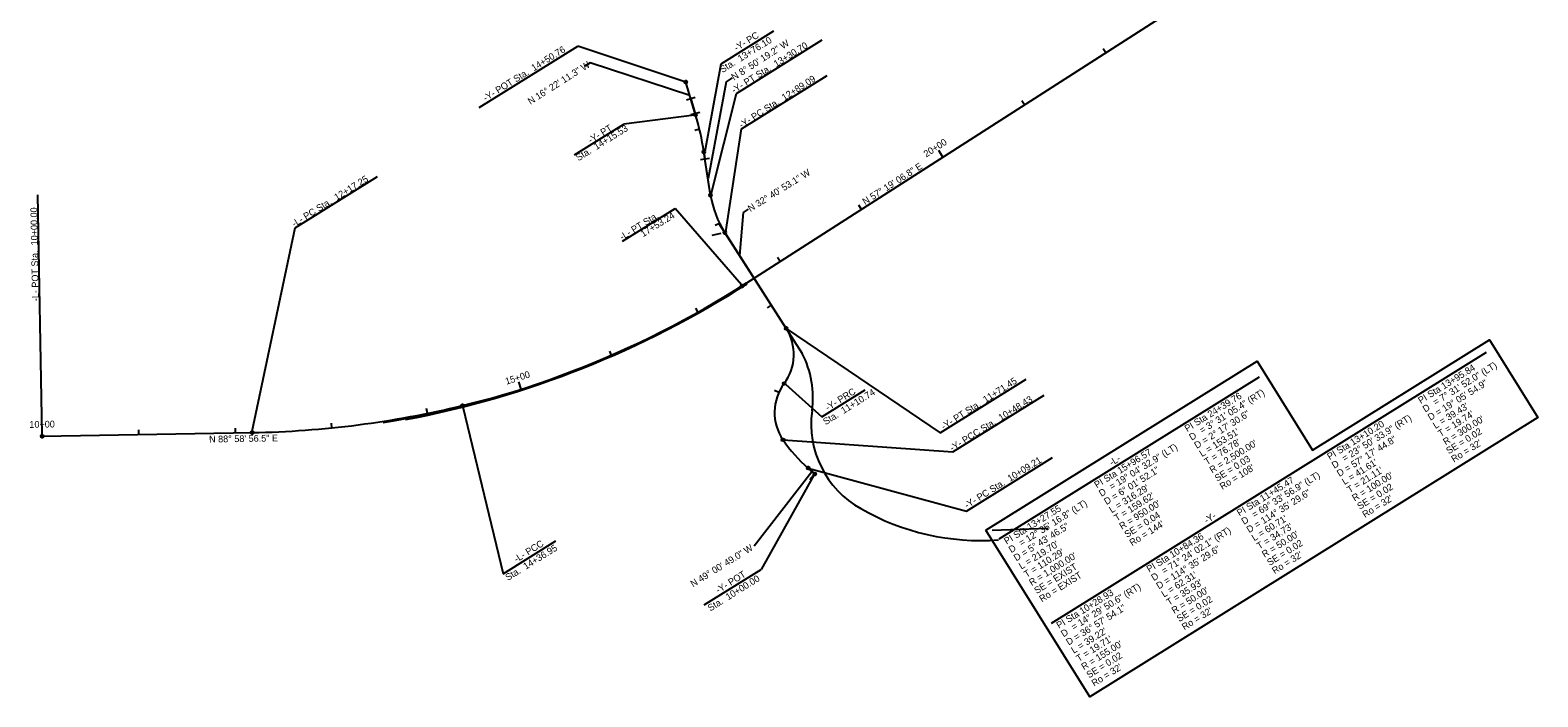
# Model space of a CAD drawing. Extents: x 2045940 to 2048976, y 757914 to 760106.
# Drawn here: x 2045940 to 2047500, y 757925 to 758615 of the extents above; entities that cross this region are included whole.
import ezdxf

# ---------------------------------------------------------------- set-up
doc = ezdxf.new("R2010")
doc.units = 0
for name, color, linetype in [('Prop AutoTurn Projected Path', 7, 'Continuous'), ('Prop Conc 1ft 6in Curb and Gutter', 7, 'Continuous'), ('Prop Conc 5in Monolithic Surface Mount Island', 7, 'Continuous'), ('Prop Dimension', 7, 'Continuous'), ('Prop Horizontal Alignment', 7, 'Continuous'), ('Prop Lane Lines', 7, 'Continuous'), ('Prop Paint Stripe', 7, 'Continuous'), ('Prop Superelevation  Arrow CELL', 7, 'Continuous'), ('Prop Superelevation Label', 7, 'Continuous'), ('Prop Terminator CELL', 7, 'Continuous'), ('Typical Terminator CELL', 7, 'Continuous')]:
    doc.layers.add(name, color=color, linetype=linetype)

msp = doc.modelspace()

# ---------------------------------------------------------------- linework, layer by layer
at = {"layer": 'Prop AutoTurn Projected Path'}
for p, q in [((2046997.2, 758001.6), (2047447, 758281.9)), ((2046943, 758088.8), (2047212.1, 758256.4))]:
    msp.add_line(p, q, dxfattribs=at)
at = {"layer": 'Prop Conc 1ft 6in Curb and Gutter'}
for p, q in [((2046655.2, 758580.3), (2046709.9, 758614.3)), ((2046671.1, 758549.4), (2046759.9, 758604.8)), ((2046404.8, 758535), (2046506.9, 758598.5)), ((2046618.9, 758561.3), (2046506.9, 758598.5)), ((2046623, 758547.3), (2046519.8, 758581.2)), ((2046638.7, 758489.8), (2046655.2, 758580.3)), ((2046676.2, 758512.9), (2046765.1, 758568.2)), ((2046645, 758445.5), (2046671.1, 758549.4)), ((2046627.4, 758527.1), (2046554.5, 758517.6)), ((2046503.6, 758485.9), (2046554.5, 758517.6)), ((2046660.3, 758406.4), (2046676.2, 758512.9)), ((2046214.5, 758410.4), (2046299.8, 758463.5)), ((2045952.9, 758196.4), (2045948.5, 758444.8)), ((2046553.4, 758396.7), (2046607.7, 758430.5)), ((2046676.3, 758351.6), (2046607.7, 758430.5)), ((2046170.1, 758200.2), (2046214.5, 758410.4)), ((2046722.6, 758306.5), (2046881.9, 758198.6)), ((2046721.8, 758248.7), (2046759.3, 758214.9)), ((2046759.3, 758214.9), (2046804.4, 758242.9)), ((2046881.9, 758198.6), (2046970.8, 758254)), ((2046895.1, 758178.7), (2046989.3, 758237.3)), ((2046387.9, 758225.3), (2046429.7, 758052.7)), ((2046719.3, 758191.2), (2046895.1, 758178.7)), ((2046909.1, 758117.6), (2046998, 758173)), ((2046751.3, 758154.8), (2046696.6, 758057.2)), ((2046745.3, 758162), (2046909.1, 758117.6)), ((2046429.7, 758052.7), (2046484.4, 758086.7)), ((2046637.7, 758020.5), (2046696.6, 758057.2))]:
    msp.add_line(p, q, dxfattribs=at)
for centre in [(2046618.9, 758561.3), (2046628.8, 758527.5), (2046637.4, 758489), (2046644.4, 758444.2), (2046659, 758405.6), (2046677.1, 758350.4), (2046722.6, 758306.5), (2046720.5, 758249.5), (2046387.6, 758226.6), (2045952.9, 758194.9), (2046170.1, 758198.7), (2046719.3, 758191.2), (2046745.3, 758162), (2046752.3, 758156)]:
    msp.add_circle(centre, 1.5, dxfattribs=at)
at = {"layer": 'Prop Dimension'}
for p, q in [((2046884.8, 758483.6), (2046880.5, 758490.4)), ((2046448.3, 758243.5), (2046445.9, 758251.1)), ((2045952.9, 758194.9), (2045952.8, 758202.9)), ((2046752.3, 758156), (2046747, 758149.9))]:
    msp.add_line(p, q, dxfattribs=at)
at = {"layer": 'Prop Horizontal Alignment'}
for p, q in [((2046677.1, 758350.4), (2047190.3, 758679.6)), ((2046628.8, 758527.5), (2046618.9, 758561.3)), ((2046628.8, 758527.5), (2046623.9, 758544.1)), ((2046644.4, 758444.2), (2046637.4, 758489)), ((2046644.4, 758444.2), (2046637.4, 758489)), ((2046644.4, 758444.2), (2046638.5, 758481.8)), ((2046659, 758405.6), (2046722.6, 758306.5)), ((2046722.6, 758306.5), (2046659, 758405.6)), ((2046722.6, 758306.5), (2046659, 758405.6)), ((2045952.9, 758194.9), (2046170.1, 758198.7)), ((2046745.3, 758162), (2046752.3, 758156)), ((2046752.3, 758156), (2046745.3, 758162)), ((2046752.3, 758156), (2046745.3, 758162))]:
    msp.add_line(p, q, dxfattribs=at)
for centre, radius, start, end in [((2046341, 758443), 300, 8.8387, 16.3698), ((2046743.2, 758459.6), 100, 188.8387, 212.6814), ((2046743.2, 758459.6), 100, 188.8387, 212.6814), ((2046164.1, 759150), 950, 283.6056, 302.6814), ((2046680.5, 758279.5), 50, 323.1156, 32.6814), ((2046680.5, 758279.5), 50, 323.1156, 32.6814), ((2046760.5, 758219.5), 50, 143.1156, 214.5162), ((2046760.5, 758219.5), 50, 143.1156, 214.5162), ((2046152.4, 759198.6), 1000, 271.0176, 283.6056), ((2046847, 758279), 155, 214.5162, 229.0136), ((2046847, 758279), 155, 214.5162, 229.0136)]:
    msp.add_arc(centre, radius, start, end, dxfattribs=at)
at = {"layer": 'Prop Lane Lines'}
for p, q in [((2046519.8, 758581.2), (2046514.3, 758577.8)), ((2046660.4, 758561.6), (2046641.7, 758461.6)), ((2046666.7, 758565.6), (2046660.4, 758561.6)), ((2046683.4, 758429.8), (2046678, 758426.4)), ((2046678, 758426.4), (2046674.2, 758382)), ((2046689.4, 758081.6), (2046749.2, 758158.6))]:
    msp.add_line(p, q, dxfattribs=at)
at = {"layer": 'Prop Paint Stripe'}
for p, q in [((2046619.4, 758542.8), (2046628.5, 758545.5)), ((2046623.9, 758544.1), (2046628.8, 758527.5)), ((2046623.8, 758527.6), (2046633.1, 758530)), ((2046633.8, 758481.1), (2046643.3, 758482.6)), ((2046637.4, 758489), (2046638.5, 758481.8)), ((2046653, 758415), (2046739.2, 758280.7)), ((2046646, 758403.1), (2046655.3, 758404.9)), ((2046993.1, 758099.6), (2046935.6, 758097.3))]:
    msp.add_line(p, q, dxfattribs=at)
for centre, radius, start, end in [((2046341, 758443), 300, 8.8387, 16.3698), ((2046650.3, 758234.8), 100, 352.1245, 27.3234), ((2046848.4, 758207.5), 100, 172.1685, 240.9108), ((2046923.9, 758337.1), 250, 240.2392, 274.1799)]:
    msp.add_arc(centre, radius, start, end, dxfattribs=at)
at = {"layer": 'Prop Superelevation  Arrow CELL'}
msp.add_arc((2046143.4, 759192.8), 997, 279.3677, 302.668, dxfattribs=at)
at = {"layer": 'Prop Superelevation Label'}
msp.add_lwpolyline([(2046929.2, 758097.8), (2047209.9, 758272.6), (2047267.2, 758180.5), (2047450.3, 758294.6), (2047500.2, 758214.2), (2047036.6, 757925.4)], close=True, dxfattribs=at)
at = {"layer": 'Prop Terminator CELL'}
for p, q in [((2047053.1, 758591.6), (2047050.4, 758595.8)), ((2046969, 758537.6), (2046966.3, 758541.8)), ((2046632.8, 758512.5), (2046627.9, 758511.3)), ((2046800.6, 758429.6), (2046797.9, 758433.8)), ((2046653.7, 758415), (2046649.2, 758412.8)), ((2046716.4, 758375.6), (2046713.7, 758379.8)), ((2046631.5, 758322.9), (2046629, 758327.3)), ((2046707.1, 758330.6), (2046702.9, 758327.9)), ((2046542, 758278.4), (2046540, 758283)), ((2046715, 758240.3), (2046710.4, 758242.4)), ((2046351.5, 758218.6), (2046350.5, 758223.5)), ((2046052.9, 758196.7), (2046052.8, 758201.7)), ((2046152.9, 758198.4), (2046152.8, 758203.4)), ((2046252.7, 758203.6), (2046252.2, 758208.6))]:
    msp.add_line(p, q, dxfattribs=at)
at = {"layer": 'Typical Terminator CELL'}
msp.add_arc((2046143.4, 759192.8), 998, 280.7088, 302.668, dxfattribs=at)

# ---------------------------------------------------------------- texts
at = {"layer": 'Prop AutoTurn Projected Path'}
for s, rotation, p in [('PI Sta 13+95.84', 31.9183, (2047379, 758228.3)), ('= 7%%d 31\' 52.0" (LT)', 31.9183, (2047394.4, 758226.5)), ('= 3%%d 31\' 05.4" (RT)', 31.9194, (2047152.8, 758197.4)), ('D = 19%%d 05\' 54.9"', 31.9183, (2047389, 758210.9)), ('PI Sta 24+39.76', 31.9194, (2047137.4, 758199.2)), ('D', 31.9183, (2047383.7, 758219.4)), ("L = 39.43'", 31.9183, (2047394.3, 758202.4)), ('D = 2%%d 17\' 30.6"', 31.9194, (2047147.4, 758181.8)), ('PI Sta 13+10.20', 31.9183, (2047284.9, 758170.2)), ('= 23%%d 50\' 33.9" (RT)', 31.9183, (2047300.3, 758168.4)), ("T = 19.74'", 31.9183, (2047399.6, 758194)), ("R = 300.00'", 31.9183, (2047404.8, 758185.5)), ('D', 31.9194, (2047142.1, 758190.3)), ("L = 153.51'", 31.9194, (2047152.7, 758173.3)), ('D = 57%%d 17\' 44.8"', 31.9183, (2047294.9, 758152.8)), ('SE = 0.02', 31.9194, (2047408, 758176.2)), ('PI Sta 15+96.57', 31.9194, (2047044, 758141)), ('= 19%%d 04\' 32.9" (LT)', 31.9194, (2047059.5, 758139.2)), ("T = 76.78'", 31.9194, (2047157.9, 758164.9)), ("R = 2,500.00'", 31.9194, (2047163.2, 758156.4)), ("Ro = 32'", 31.9194, (2047413.3, 758167.7)), ('D = 6%%d 01\' 52.1"', 31.9194, (2047054, 758123.7)), ('-L-', 31.9194, (2047059.5, 758164.1)), ('SE = 0.03', 31.9194, (2047168.5, 758147.9)), ("Ro = 108'", 31.9194, (2047173.8, 758139.4)), ('D', 31.9183, (2047289.6, 758161.3)), ("L = 41.61'", 31.9183, (2047300.2, 758144.4)), ("T = 21.11'", 31.9183, (2047305.5, 758135.9)), ('PI Sta 11+45.47', 31.9183, (2047191.5, 758112)), ('= 69%%d 33\' 56.9" (LT)', 31.9183, (2047207, 758110.2)), ("R = 100.00'", 31.9183, (2047310.7, 758127.4)), ('D', 31.9194, (2047048.7, 758132.2)), ("L = 316.29'", 31.9194, (2047059.3, 758115.2)), ("T = 159.62'", 31.9194, (2047064.6, 758106.7)), ('D = 114%%d 35\' 29.6"', 31.9183, (2047201.5, 758094.7)), ('SE = 0.02', 31.9194, (2047316, 758118.9)), ("Ro = 32'", 31.9194, (2047321.3, 758110.4)), ('PI Sta 13+27.55', 31.9194, (2046950.6, 758082.8)), ('= 12%%d 35\' 16.8" (LT)', 31.9194, (2046966.1, 758081)), ("R = 950.00'", 31.9194, (2047069.9, 758098.2)), ('SE = 0.04', 31.9194, (2047075.2, 758089.7)), ('D = 5%%d 43\' 46.5"', 31.9194, (2046960.6, 758065.5)), ("Ro = 144'", 31.9194, (2047080.4, 758081.2)), ('-Y-', 31.9194, (2047157.5, 758104.3)), ('D', 31.9183, (2047196.2, 758103.2)), ("L = 60.71'", 31.9183, (2047206.8, 758086.2)), ("T = 34.73'", 31.9183, (2047212.1, 758077.7)), ("L = 219.70'", 31.9194, (2046965.9, 758057)), ('PI Sta 10+84.36', 31.9183, (2047098.1, 758053.9)), ('= 71%%d 24\' 02.1" (RT)', 31.9183, (2047113.6, 758052.1)), ("R = 50.00'", 31.9183, (2047217.4, 758069.2)), ('SE = 0.02', 31.9194, (2047222.7, 758060.7)), ('D', 31.9194, (2046955.4, 758074)), ("T = 110.29'", 31.9194, (2046971.2, 758048.5)), ("R = 1,000.00'", 31.9194, (2046976.5, 758040)), ('D = 114%%d 35\' 29.6"', 31.9183, (2047108.1, 758036.5)), ("Ro = 32'", 31.9194, (2047227.9, 758052.2)), ('SE = EXIST', 31.9194, (2046981.8, 758031.6)), ('Ro = EXIST', 31.9194, (2046987.1, 758023.1)), ("L = 62.31'", 31.9183, (2047113.4, 758028)), ('= 14%%d 29\' 50.6" (RT)', 31.9183, (2047020.2, 757993.9)), ('D', 31.9183, (2047102.9, 758045)), ("T = 35.93'", 31.9183, (2047118.7, 758019.6)), ("R = 50.00'", 31.9183, (2047124, 758011.1)), ('PI Sta 10+28.93', 31.9183, (2047004.8, 757995.7)), ('SE = 0.02', 31.9194, (2047129.3, 758002.6)), ('D = 36%%d 57\' 54.1"', 31.9183, (2047014.8, 757978.4)), ("Ro = 32'", 31.9194, (2047134.6, 757994.1)), ('D', 31.9183, (2047009.5, 757986.9)), ("L = 39.22'", 31.9183, (2047020.1, 757969.9)), ("T = 19.71'", 31.9183, (2047025.3, 757961.4)), ("R = 155.00'", 31.9183, (2047030.6, 757952.9)), ('SE = 0.02', 31.9194, (2047035.9, 757944.4)), ("Ro = 32'", 31.9194, (2047041.2, 757935.9))]:
    msp.add_text(s, height=7, rotation=rotation, dxfattribs=at).set_placement(p)
at = {"layer": 'Prop Conc 1ft 6in Curb and Gutter'}
for s, rotation, p in [(' Sta.  13+76.10', 31.9194, (2046654.4, 758569.1)), ('-Y- PT Sta.  13+30.70', 31.9194, (2046668.6, 758549.3)), ('-Y- PC', 31.9194, (2046671.3, 758593)), ('-Y- POT Sta.  14+50.76', 31.9194, (2046411.7, 758541.2)), ('-Y- PC Sta.  12+89.09', 32.6814, (2046676.5, 758513.3)), ('Sta.  14+15.53', 31.9194, (2046507.7, 758479.3)), ('-Y- PT ', 31.9194, (2046520.3, 758497.6)), ('-L- PC Sta.  12+17.25', 31.9194, (2046213.9, 758411.2)), ('-L- POT Sta.  10+00.00', 91.0176, (2045949.4, 758334.7)), ('-L- PT Sta.  ', 31.9194, (2046553, 758397.5)), ('17+53.24', 31.9194, (2046574.6, 758400.7)), ('Sta.  11+10.74', 31.9194, (2046763.4, 758206.3)), ('-Y- PRC ', 31.9194, (2046765.6, 758221)), ('-Y- PT Sta.  11+71.45', 32.6814, (2046885.6, 758201.4)), ('-Y- PCC Sta.  10+48.43', 31.9194, (2046894.5, 758179.2)), ('-Y- PC Sta.  10+09.21', 31.9183, (2046909.6, 758119.9)), ('-L- PCC ', 31.9194, (2046443.7, 758064.2)), ('Sta.  14+36.95', 31.9194, (2046434.7, 758045.2)), ('-Y- POT ', 31.9194, (2046652.4, 758032.2)), ('Sta.  10+00.00', 31.9194, (2046644.1, 758013.6))]:
    msp.add_text(s, height=7, rotation=rotation, dxfattribs=at).set_placement(p)
at = {"layer": 'Prop Conc 5in Monolithic Surface Mount Island'}
for s, rotation, p in [('20+00', 32.6814, (2046867.5, 758483.2)), ('15+00', 17.4081, (2046433.1, 758248.2)), ('10+00', 1.0176, (2045939.7, 758203.6))]:
    msp.add_text(s, height=7, rotation=rotation, dxfattribs=at).set_placement(p)
at = {"layer": 'Prop Lane Lines'}
for s, rotation, p in [('N 8%%d 50\' 19.2" W', 32.6814, (2046668.6, 758562.7)), ('N 16%%d 22\' 11.3" W', 32.4944, (2046458, 758537.7)), ('N 57%%d 19\' 06.8" E', 32.6814, (2046804.2, 758434)), ('N 32%%d 40\' 53.1" W', 31.918, (2046685.6, 758426.8)), ('N 88%%d 58\' 56.5" E', 1.0176, (2046125.6, 758188.4)), ('N 49%%d 00\' 49.0" W', 31.9194, (2046626.2, 758038.6))]:
    msp.add_text(s, height=7, rotation=rotation, dxfattribs=at).set_placement(p)

doc.saveas('drawing.dxf')
